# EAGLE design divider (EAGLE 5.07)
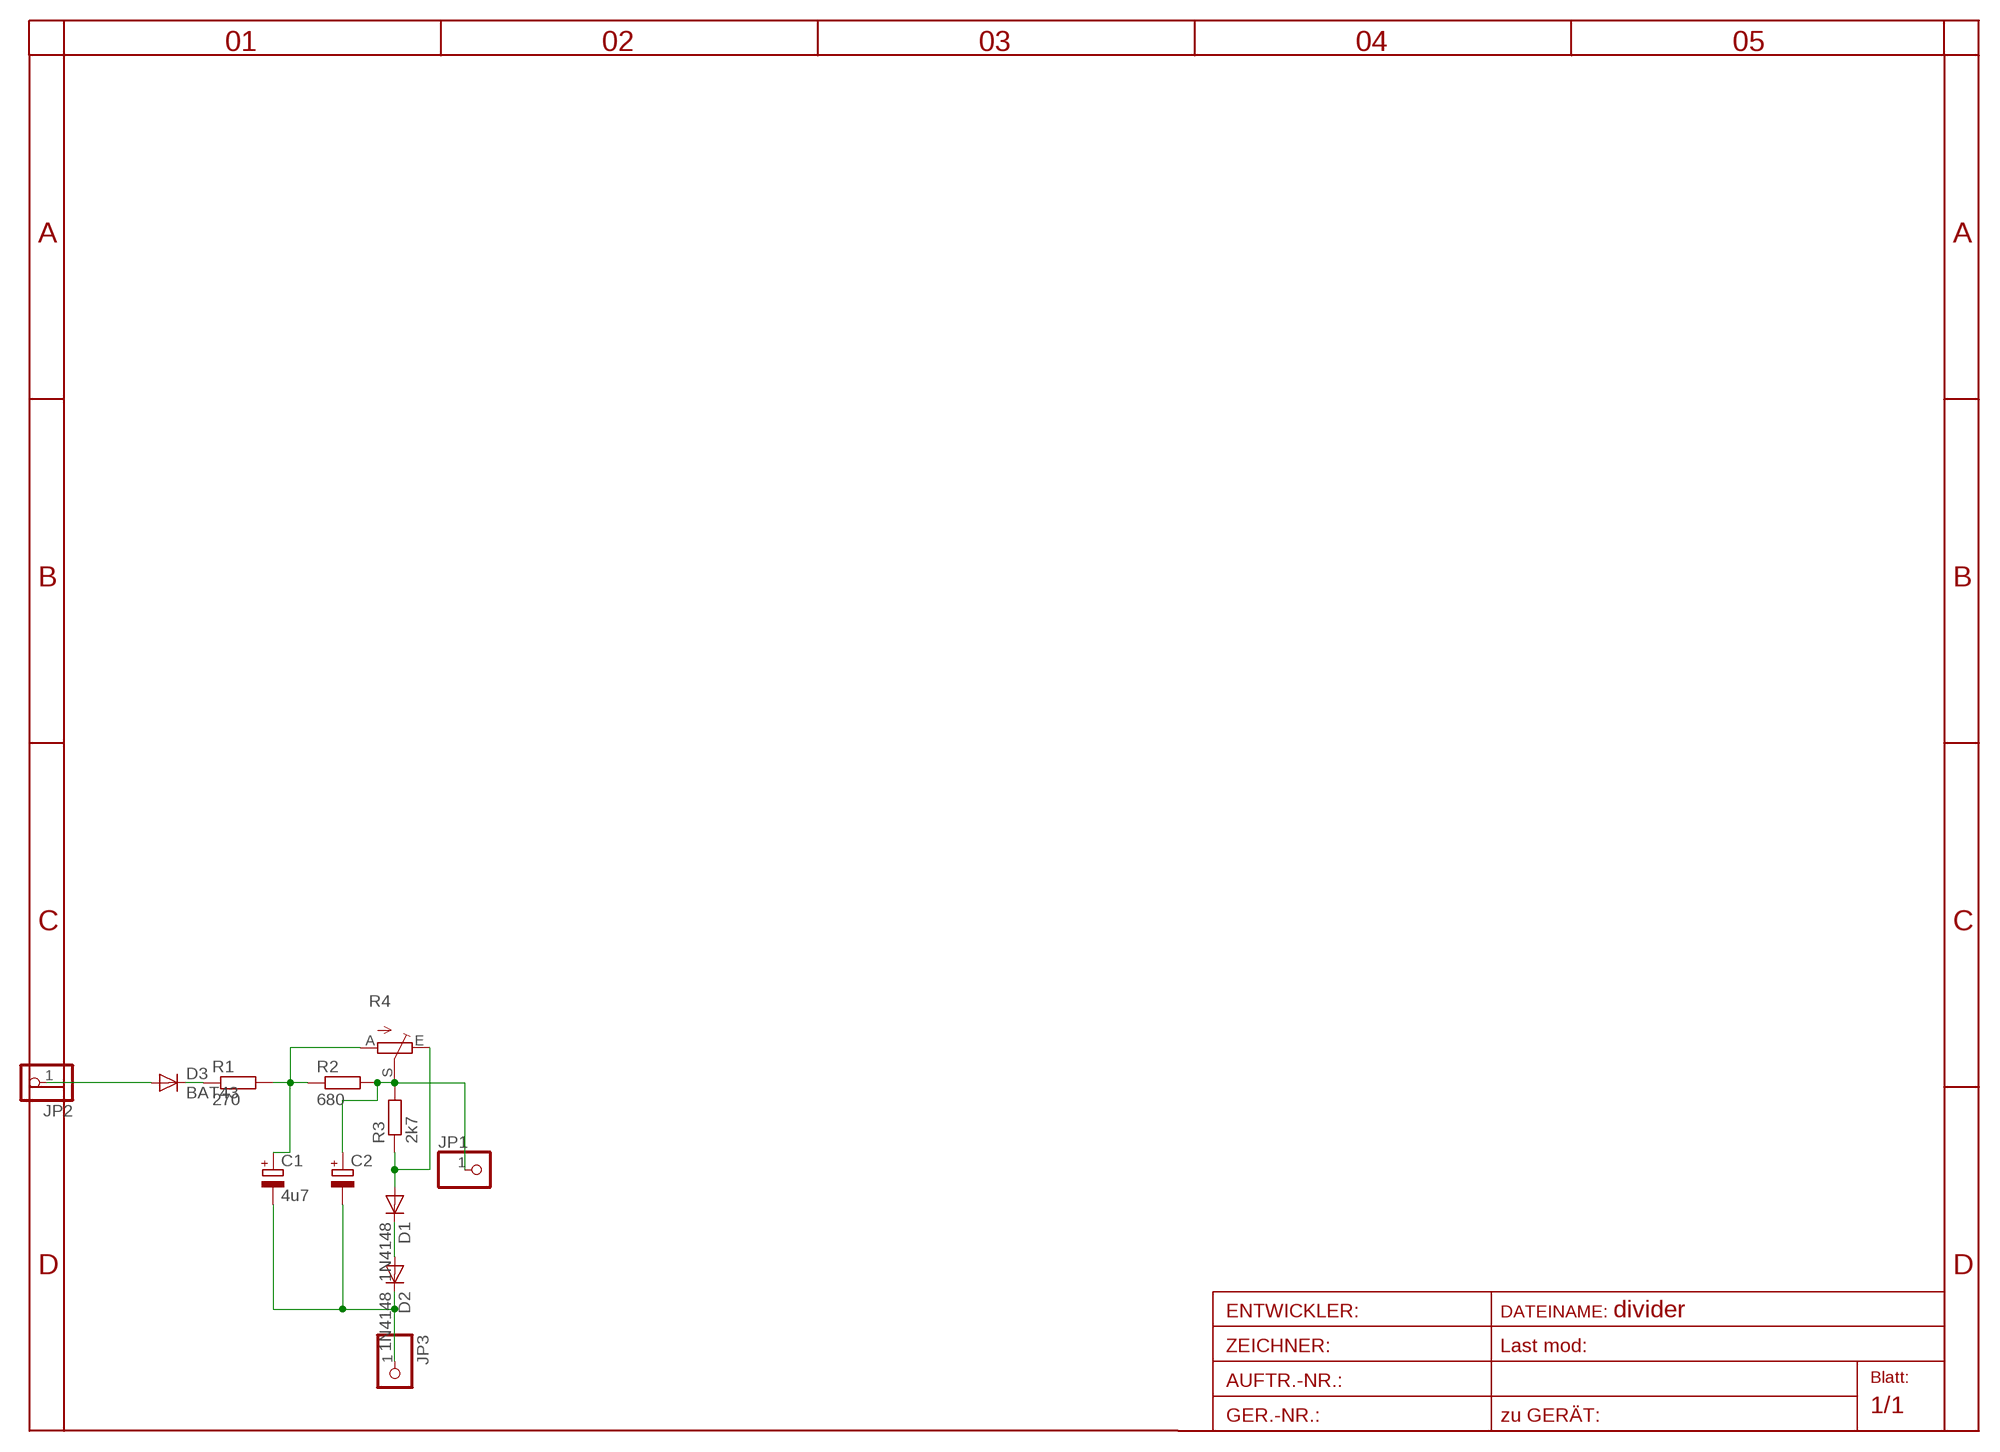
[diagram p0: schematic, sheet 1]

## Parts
C1  4u7  CPOL-EUSMCA  [SMC_A]
C2  CPOL-EUSMCA  [SMC_A]
D1  1N4148  DIODE-SOD80C  [SOD80C]
D2  1N4148  DIODE-SOD80C  [SOD80C]
D3  BAT43  DIODE-SOD80C  [SOD80C]
JP1  PINHD-1X11X0.4  [1X01]
JP2  PINHD-1X11X0.4  [1X01]
JP3  PINHD-1X11X0.4  [1X01]
R1  270  R-EU_R0805  [R0805]
R2  680  R-EU_R0805  [R0805]
R3  2k7  R-EU_R0805  [R0805]
R4  TRIM_EU-CA6V  [CA6V]

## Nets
DR1: D3.C R1.1
DR2: D1.A R3.1 R4.E
GND: C1.- C2.- D2.C JP3.1
IN: D3.A JP2.1
N$2: D1.C D2.A
OUT: C2.+ JP1.1 R2.2 R3.2 R4.S
RRC: C1.+ R1.2 R2.1 R4.A

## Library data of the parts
C1 C2 = rcl:CPOL-EU: POLARIZED CAPACITOR, European symbol
D1-D3 = diode:DIODE-: DIODE
JP1-JP3 = pinhead:PINHD-1X1: PIN HEADER
R1-R3 = rcl:R-EU_: RESISTOR, European symbol
R4 = pot:TRIM_EU-: POTENTIOMETER

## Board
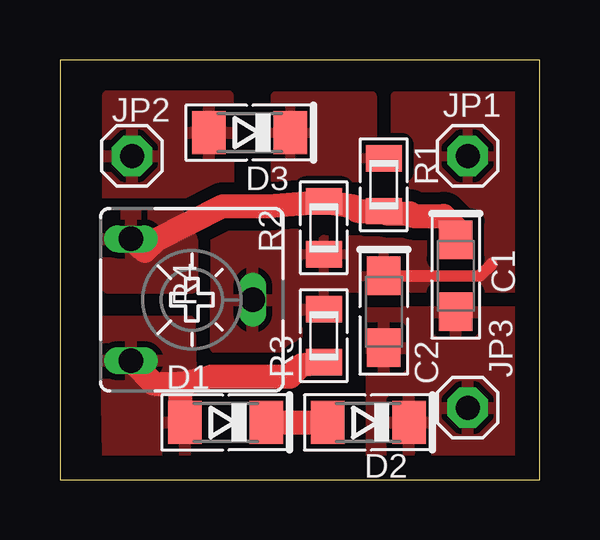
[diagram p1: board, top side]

Size 20 x 17.5 mm. Coordinates in mm from the lower left corner, seen from the top.
Outline: 0,0 20,0 20,17.5 0,17.5 0,0
Copper layers (1*16): Top 0.035mm / dielectric 1.5mm / Bottom 0.035mm
Design rules "default": minimum track width 10mil, minimum drill 20mil, track to track 8mil, track to pad 8mil, pad to pad 8mil, via to via 8mil, smd to smd 8mil, copper to edge 40mil, drill to drill 8mil, minimum pad ring 1mil, minimum via ring 8mil, stop-mask expansion 4mil, vias tented up to drill 0mil, thermal gap 10mil

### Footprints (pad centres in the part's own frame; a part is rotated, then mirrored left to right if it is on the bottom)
SMC_A = smd 1.6 x 1.4: + -1.5,0; - 1.5,0
SOD80C = smd 1.4 x 1.8: A 1.7,0; C -1.7,0
1X01 = drill 1 pad 1.676 octagon: 1 0,0
R0805 = smd 1.1 x 1.5: 1 -1.1,0; 2 1.1,0
CA6V = drill 1.016 long: A -2.54,-2.54; E 2.54,-2.54; S 0,2.54

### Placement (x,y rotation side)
C1  16.5,8.5 270 top
C2  13.5,7 270 top
D1  6.91,2.38 180 top
D2  12.86,2.38 180 top
D3  7.91,14.47 180 top
JP1  17,13.5 0 top
JP2  3,13.5 0 top
JP3  17,3 0 top
R1  13.5,12.3 270 top
R2  11,10.5 270 top
R3  11,6 90 top
R4  5.5,7.5 270 top

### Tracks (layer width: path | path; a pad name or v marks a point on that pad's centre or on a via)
DR1
  pour Top (isolate 0.5): 9,16 13,16 13,12.5 9,12.5
DR2
  Top 1: R3.1 10.08,4.78 9.6,4.3 6.3,4.3 5,4 | 5,4 3.92,4 R4.E | 5,4 5,2.57 D1.A
  pour Top (isolate 0.5, rank 3): 1.9,6.6 5.4,6.6 5.5,1 2,1
GND
  pour Top (isolate 0.5, rank 3): 13,7 19,7 19,1 13,1
IN
  pour Top (isolate 0.5, rank 3): 2,16 7,16 7,12 2,10
N$2
  Top 1: D1.C D2.A
OUT
  Top 0.5: C2.+ 17.51,8.51 18,9
  pour Top (isolate 0.5, rank 2): 14,16 19,16 19,8 12,8 11,7 9,8 9,9 11,10 17,10 17,11 14,11
  pour Top (isolate 0.5, rank 4): 6.5,10.5 9.7,10.4 10,8 10,5.5 6.5,5.5
RRC
  Top 1: R4.A 3.54,9.54 4,10 6.8,11.4 8.7,11.4 R2.1 12.2,11.4 12.4,11.2 R1.2 13.6,11.1 14.6,11.1 14.7,11 16,11 16.5,10.5 C1.+
  pour Top (isolate 0.5, rank 2): 2,11 5,11 5.5,10 5.5,8 2,8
